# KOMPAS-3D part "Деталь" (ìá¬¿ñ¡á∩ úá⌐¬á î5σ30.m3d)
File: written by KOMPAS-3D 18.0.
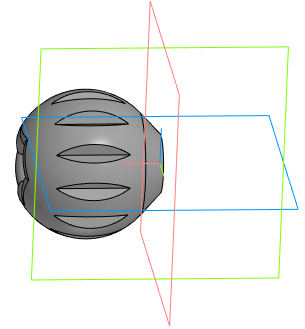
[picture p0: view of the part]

Document properties: Автор: Пользователь Windows; Полное имя файла: F:\Модели\Мех детали\Велосипед\Крепление фонаря\2\Накидная гайка М5х30.m3d

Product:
- Part/product: Деталь
    Масса: 0.0981276

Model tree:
1. Эскиз:1
2. Элемент вращения:1
     Угол 1 = 360
3. Эскиз:2  (with: Элемент вращения:1)
4. Элемент выдавливания:1
     Расстояние 1 = 30
5. Скругление:1  (with: Элемент вращения:1)
     Радиус = 2
6. Эскиз:3
7. Элемент выдавливания:2
     Расстояние 1 = 30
